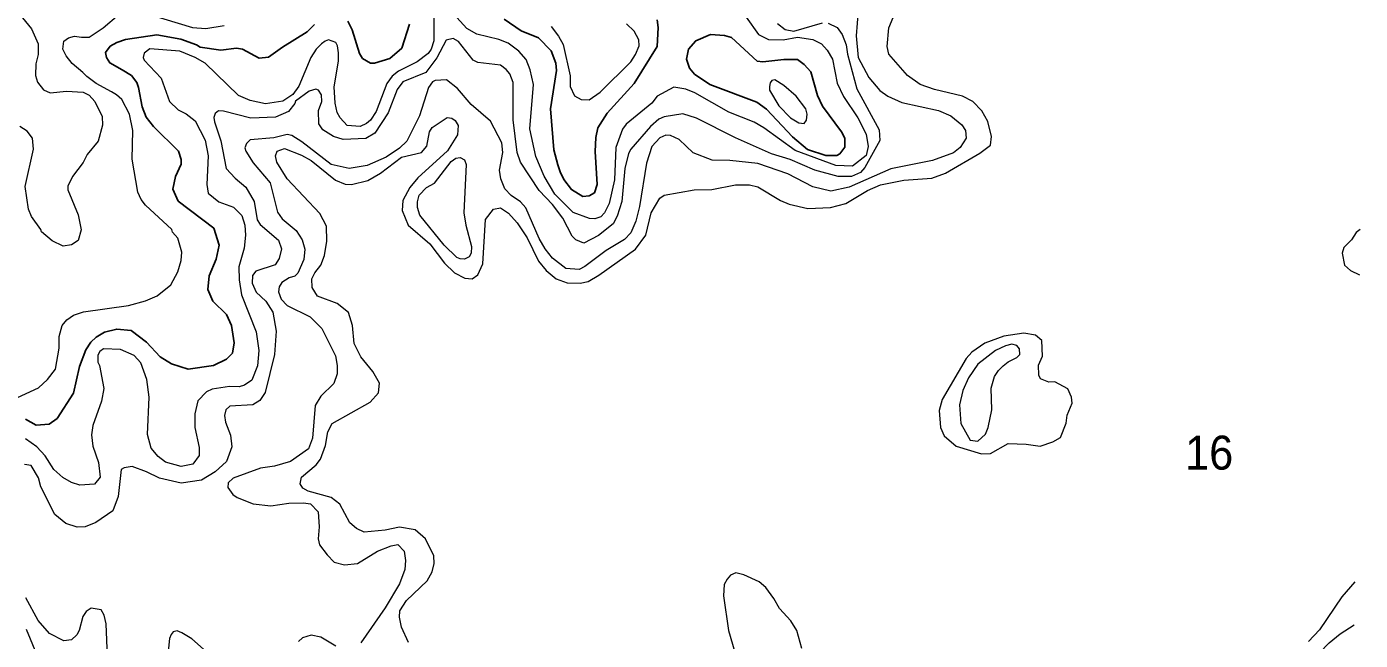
# Model space of a CAD drawing. Extents: x 673.6 to 698.9, y 7012 to 7040.1.
# Drawn here: x 695.502 to 698.642, y 7022.853 to 7024.299 of the extents above; entities that cross this region are included whole.
import ezdxf

# ---------------------------------------------------------------- set-up
doc = ezdxf.new("R2010")
doc.units = 0
doc.header["$LTSCALE"] = 0.032
doc.layers.add('1', color=7, linetype='Continuous', lineweight=25)
doc.layers.add('2', color=7, linetype='Continuous', lineweight=13)
doc.layers.add('21', color=7, linetype='Continuous')

msp = doc.modelspace()

# ---------------------------------------------------------------- linework, layer by layer
at = {"layer": '1'}
for points in [[(696.1792, 7024.3044), (696.1622, 7024.2869), (696.1045, 7024.2508), (696.0713, 7024.2273), (696.0491, 7024.2248), (696.0104, 7024.2458), (695.9957, 7024.2489), (695.9587, 7024.2442), (695.9107, 7024.2506), (695.9017, 7024.2566), (695.8651, 7024.2694), (695.8083, 7024.2802)], [(696.4032, 7024.3049), (696.385, 7024.2488), (696.3572, 7024.2244), (696.3212, 7024.2129), (696.3116, 7024.2129), (696.2926, 7024.2243), (696.2853, 7024.2361), (696.2684, 7024.2918), (696.2584, 7024.3118)], [(696.9865, 7024.3152), (696.9891, 7024.2971), (696.9867, 7024.2521), (696.9322, 7024.1649), (696.8686, 7024.0955), (696.8465, 7024.0609), (696.842, 7024.0379), (696.8405, 7024.005), (696.8453, 7023.9273), (696.839, 7023.9079), (696.8265, 7023.901), (696.8112, 7023.899), (696.7846, 7023.9155), (696.7667, 7023.939), (696.758, 7023.9571), (696.7523, 7023.9738), (696.7435, 7024.0088), (696.7353, 7024.1053), (696.7492, 7024.1963), (696.7482, 7024.2129), (696.7369, 7024.2421), (696.707, 7024.2731), (696.6666, 7024.2892), (696.6259, 7024.3167)], [(695.8083, 7024.2802), (695.7347, 7024.2688), (695.7138, 7024.2615), (695.6981, 7024.253), (695.6876, 7024.238), (695.6897, 7024.2263)], [(695.6897, 7024.2263), (695.6975, 7024.2139), (695.727, 7024.1973), (695.749, 7024.1839), (695.7615, 7024.1673), (695.7649, 7024.1555), (695.7735, 7024.1102), (695.7831, 7024.086), (695.8002, 7024.0638), (695.8593, 7024.0062), (695.8658, 7023.9862), (695.8658, 7023.9754), (695.8525, 7023.9463), (695.8462, 7023.9167), (695.8588, 7023.8884), (695.9428, 7023.8244), (695.9551, 7023.7841), (695.9481, 7023.7514), (695.9318, 7023.7125), (695.9283, 7023.6796), (695.9404, 7023.6528), (695.972, 7023.621), (695.9841, 7023.5949), (695.9907, 7023.5542), (695.9863, 7023.53), (695.9723, 7023.5159), (695.9418, 7023.5006), (695.8822, 7023.4923), (695.8432, 7023.5052), (695.8158, 7023.521), (695.7838, 7023.5561), (695.7475, 7023.5833), (695.7138, 7023.5867), (695.6851, 7023.5793), (695.6654, 7023.5677), (695.6525, 7023.5557), (695.6414, 7023.5379), (695.6262, 7023.4989), (695.6119, 7023.4356), (695.5738, 7023.3761), (695.5548, 7023.3623), (695.5243, 7023.36), (695.4987, 7023.3741)]]:
    msp.add_lwpolyline(points, dxfattribs=at)
msp.add_lwpolyline([(697.285, 7024.2219), (697.2352, 7024.2162), (697.2221, 7024.2178), (697.1613, 7024.2737), (697.1452, 7024.2786), (697.1121, 7024.281), (697.0775, 7024.2656), (697.0601, 7024.2465), (697.0558, 7024.2228), (697.0628, 7024.2016), (697.0742, 7024.1873), (697.1108, 7024.1631), (697.2209, 7024.1211), (697.2438, 7024.1046), (697.305, 7024.04), (697.3402, 7024.0095), (697.3837, 7023.9955), (697.4092, 7023.9959), (697.4165, 7023.9994), (697.4288, 7024.0155), (697.4288, 7024.0366), (697.4209, 7024.0516), (697.3756, 7024.112), (697.3642, 7024.1369), (697.3481, 7024.1931), (697.3326, 7024.2104), (697.317, 7024.2218)], close=True, dxfattribs=at)
at = {"layer": '2'}
for points in [[(697.4624, 7024.3678), (697.455, 7024.2774)], [(695.4804, 7023.4259), (695.5294, 7023.4485), (695.551, 7023.4682), (695.57, 7023.4925), (695.5782, 7023.542), (695.5784, 7023.5694), (695.5857, 7023.5949), (695.5961, 7023.6086), (695.6118, 7023.6197), (695.6354, 7023.6277), (695.7417, 7023.6419), (695.7817, 7023.6531), (695.809, 7023.6651), (695.8416, 7023.691), (695.8575, 7023.7213), (695.8659, 7023.7482), (695.8674, 7023.768), (695.8574, 7023.8006), (695.8455, 7023.8151), (695.8439, 7023.8213), (695.7819, 7023.8787), (695.7712, 7023.8919), (695.7637, 7023.9096), (695.75, 7023.9874), (695.7514, 7024.0542), (695.7442, 7024.0929), (695.726, 7024.1274), (695.7134, 7024.1386), (695.7015, 7024.1457), (695.6656, 7024.1651), (695.6432, 7024.1817), (695.6339, 7024.1909), (695.6087, 7024.2121), (695.5945, 7024.2302), (695.5873, 7024.2465), (695.5896, 7024.2649), (695.6004, 7024.2732), (695.6141, 7024.2771), (695.631, 7024.2745), (695.6493, 7024.2744), (695.682, 7024.2968), (695.7185, 7024.3277)], [(695.4846, 7024.3285), (695.5131, 7024.2937), (695.5289, 7024.2585), (695.5289, 7024.2337), (695.5234, 7024.212), (695.5224, 7024.1845), (695.5275, 7024.1681), (695.5413, 7024.1504), (695.5572, 7024.1431), (695.5953, 7024.1472), (695.6346, 7024.1448), (695.6493, 7024.1376), (695.662, 7024.1232), (695.6796, 7024.0877), (695.68, 7024.0674), (695.6701, 7024.0296), (695.6442, 7023.9979), (695.6347, 7023.9792), (695.6098, 7023.9459), (695.5989, 7023.9234), (695.5991, 7023.9145), (695.6227, 7023.8559), (695.6298, 7023.8205), (695.6233, 7023.7955), (695.6077, 7023.7848), (695.5876, 7023.7824), (695.5622, 7023.7949), (695.5364, 7023.816), (695.5353, 7023.8217), (695.5132, 7023.8517), (695.5061, 7023.8691), (695.4985, 7023.9224), (695.5182, 7024.0107), (695.5155, 7024.0365), (695.5031, 7024.0528), (695.4859, 7024.0642)], [(695.757, 7024.3378), (695.8922, 7024.2972), (695.924, 7024.2951), (695.9669, 7024.3018)], [(696.4608, 7024.3308), (696.4607, 7024.2656), (696.454, 7024.2464), (696.4469, 7024.2361), (696.421, 7024.216), (696.3776, 7024.1943), (696.3623, 7024.1826), (696.3498, 7024.165), (696.3249, 7024.0993), (696.3115, 7024.0792), (696.3024, 7024.0711), (696.287, 7024.064), (696.2566, 7024.0667), (696.24, 7024.0845), (696.233, 7024.0968), (696.2281, 7024.1187), (696.2257, 7024.1575), (696.2364, 7024.2178), (696.2364, 7024.2379), (696.234, 7024.2543), (696.2297, 7024.2621), (696.2129, 7024.2678), (696.2046, 7024.2654), (696.1957, 7024.2587), (696.1835, 7024.2464), (696.171, 7024.2267), (696.1429, 7024.1591), (696.1282, 7024.1392), (696.1047, 7024.1238)], [(697.1957, 7024.3219), (697.2251, 7024.2809), (697.2484, 7024.2691), (697.283, 7024.2683), (697.3171, 7024.2744), (697.3531, 7024.2692), (697.3735, 7024.2585), (697.3871, 7024.2439), (697.3992, 7024.2227), (697.4105, 7024.1659), (697.4252, 7024.1348), (697.4593, 7024.0842), (697.4785, 7024.0463), (697.483, 7024.017), (697.4783, 7023.9956), (697.4466, 7023.9705), (697.4075, 7023.9722), (697.3112, 7024.0071), (697.2379, 7024.0612), (697.2151, 7024.074), (697.1549, 7024.0975), (697.0754, 7024.143), (697.0541, 7024.152), (697.0254, 7024.157), (696.9865, 7024.1354), (696.974, 7024.1191), (696.9138, 7024.0693), (696.9046, 7024.0576), (696.889, 7024.0144), (696.8864, 7023.9381), (696.8731, 7023.8822), (696.8622, 7023.8602), (696.8536, 7023.8514), (696.8394, 7023.8465), (696.8271, 7023.8469), (696.7885, 7023.8617), (696.7457, 7023.9049), (696.7202, 7023.9473), (696.701, 7023.9936), (696.6868, 7024.0584), (696.6949, 7024.1627), (696.6876, 7024.1978), (696.678, 7024.2217), (696.6607, 7024.2414), (696.6354, 7024.2603), (696.6134, 7024.2688), (696.5617, 7024.2817), (696.5386, 7024.2952), (696.5071, 7024.3293)], [(697.389, 7024.3073), (697.4104, 7024.297), (697.4221, 7024.2804), (697.4318, 7024.2564), (697.4349, 7024.2345), (697.457, 7024.1526), (697.509, 7024.0558), (697.511, 7024.0312), (697.4752, 7023.967), (697.465, 7023.9558), (697.4439, 7023.9461), (697.4127, 7023.9458), (697.3576, 7023.961), (697.3, 7023.9863), (697.2559, 7023.9994), (697.1713, 7024.0375), (697.0791, 7024.0837), (697.0472, 7024.0937), (697.0029, 7024.0869), (696.9908, 7024.0813), (696.971, 7024.0639), (696.9247, 7024.0107), (696.9189, 7024.0003), (696.9102, 7023.9647), (696.9035, 7023.8871), (696.892, 7023.8526), (696.8825, 7023.8348), (696.8481, 7023.8071), (696.8139, 7023.7889), (696.7951, 7023.7967), (696.7862, 7023.8059), (696.7646, 7023.8483), (696.7404, 7023.8806), (696.7087, 7023.9131), (696.6643, 7023.9801), (696.6568, 7024.0026), (696.6472, 7024.0794), (696.6474, 7024.1678), (696.6392, 7024.1879), (696.6313, 7024.1985), (696.6176, 7024.2087), (696.5644, 7024.215), (696.5531, 7024.2204), (696.519, 7024.2645), (696.5058, 7024.271), (696.4893, 7024.2675), (696.4679, 7024.2259), (696.442, 7024.191), (696.3879, 7024.1692), (696.3746, 7024.1508), (696.353, 7024.0959), (696.322, 7024.0479), (696.3004, 7024.0356), (696.2468, 7024.033), (696.2245, 7024.0402), (696.199, 7024.0559), (696.1895, 7024.0702), (696.1888, 7024.1014), (696.1969, 7024.1229), (696.1963, 7024.1388)], [(696.4003, 7023.8313), (696.4515, 7023.7874), (696.4857, 7023.7418), (696.5096, 7023.7191), (696.5335, 7023.707), (696.5508, 7023.7051), (696.5639, 7023.7146), (696.5757, 7023.7404), (696.5826, 7023.8451), (696.6011, 7023.8691), (696.6172, 7023.8725), (696.6366, 7023.8595), (696.6571, 7023.8373), (696.6801, 7023.802), (696.707, 7023.7468), (696.7249, 7023.7244), (696.7489, 7023.705), (696.7743, 7023.6958), (696.8055, 7023.6952), (696.8241, 7023.6987), (696.8492, 7023.7134), (696.9352, 7023.7751), (696.96, 7023.808), (696.9725, 7023.8605), (696.993, 7023.8953), (697.003, 7023.902), (697.0738, 7023.9145), (697.1153, 7023.9155), (697.1709, 7023.9269), (697.204, 7023.9269), (697.2236, 7023.9219), (697.2773, 7023.8893), (697.2977, 7023.8809), (697.3414, 7023.8711), (697.3947, 7023.8735), (697.4306, 7023.8825), (697.4816, 7023.9131), (697.5122, 7023.9264), (697.5675, 7023.9376), (697.633, 7023.9426), (697.6651, 7023.9539), (697.7467, 7024.0012), (697.7713, 7024.0198), (697.7739, 7024.0408), (697.7655, 7024.0758), (697.7514, 7024.1005), (697.7299, 7024.1231), (697.7058, 7024.1351), (697.6392, 7024.1513), (697.606, 7024.1629), (697.5762, 7024.1839), (697.5318, 7024.2343), (697.5283, 7024.2523), (697.5323, 7024.2964), (697.5425, 7024.3209)], [(696.7367, 7024.2994), (696.7545, 7024.2767), (696.7648, 7024.2572), (696.7813, 7024.183), (696.782, 7024.1581), (696.7921, 7024.1366), (696.8073, 7024.1275), (696.8267, 7024.1266), (696.8524, 7024.1452), (696.9248, 7024.2167), (696.9357, 7024.2335), (696.9439, 7024.2544), (696.9437, 7024.2684), (696.9324, 7024.2885), (696.9146, 7024.3055)], [(697.2696, 7024.3064), (697.2878, 7024.2925), (697.3081, 7024.2887), (697.3762, 7024.3082)], [(697.455, 7024.2774), (697.46, 7024.2264), (697.4851, 7024.1795), (697.5111, 7024.1486), (697.5297, 7024.1353), (697.5628, 7024.1203)], [(695.8987, 7024.2268), (695.8622, 7024.2416), (695.7919, 7024.247), (695.7787, 7024.2364), (695.7764, 7024.2268), (695.7782, 7024.2199), (695.8187, 7024.1776), (695.8385, 7024.1228), (695.8584, 7024.1036), (695.8774, 7024.0937), (695.8985, 7024.0774), (695.9222, 7024.0315), (695.929, 7023.9951), (695.9259, 7023.9274), (695.9294, 7023.907), (695.9545, 7023.8867), (695.9888, 7023.8737), (696.0088, 7023.8543), (696.0155, 7023.8313), (696.017, 7023.8083), (696.0137, 7023.7774), (696.0015, 7023.7334), (696.0021, 7023.703), (696.0075, 7023.6677), (696.0424, 7023.5801), (696.0482, 7023.5365), (696.0456, 7023.5005), (696.0318, 7023.4662), (696.0148, 7023.4543), (696.0019, 7023.4503), (695.9792, 7023.4511), (695.9386, 7023.4452), (695.9251, 7023.4388), (695.9048, 7023.4178), (695.8979, 7023.387), (695.8978, 7023.3545), (695.9076, 7023.3081), (695.9077, 7023.2888), (695.893, 7023.2683), (695.8654, 7023.263), (695.8286, 7023.2735), (695.8114, 7023.2868), (695.7952, 7023.3065), (695.7862, 7023.3382), (695.7902, 7023.426), (695.7845, 7023.4681), (695.7704, 7023.507), (695.7546, 7023.5242), (695.7225, 7023.5383), (695.6824, 7023.5398), (695.6738, 7023.5342), (695.6695, 7023.525), (695.6695, 7023.5089), (695.6736, 7023.5008), (695.6834, 7023.447), (695.6778, 7023.4165), (695.6578, 7023.3596), (695.6547, 7023.3372), (695.6578, 7023.3107), (695.6711, 7023.2721), (695.6751, 7023.2377), (695.6619, 7023.2211), (695.627, 7023.2193), (695.6071, 7023.2253), (695.5872, 7023.2374), (695.5661, 7023.2561), (695.5451, 7023.2879), (695.5259, 7023.3095), (695.4991, 7023.3278)], [(696.1047, 7024.1238), (696.0643, 7024.1176), (696.0278, 7024.1249), (696.0008, 7024.1374), (695.9219, 7024.2135), (695.8987, 7024.2268)], [(697.5628, 7024.1203), (697.6487, 7024.102), (697.6781, 7024.0894), (697.7041, 7024.0682), (697.7124, 7024.0548), (697.7144, 7024.0363), (697.7002, 7024.0144), (697.6846, 7024.0018), (697.6346, 7023.9837), (697.537, 7023.9646), (697.4383, 7023.921), (697.3956, 7023.9113), (697.3532, 7023.922), (697.294, 7023.9523), (697.2233, 7023.977), (697.1576, 7023.9836), (697.1161, 7023.9843), (697.0711, 7024.0019), (697.0381, 7024.0331), (697.0181, 7024.0427), (697.0067, 7024.0433), (696.9931, 7024.0375), (696.9741, 7024.0172), (696.9617, 7023.9777), (696.945, 7023.8755), (696.9362, 7023.8408), (696.9242, 7023.8136), (696.9096, 7023.7975), (696.8665, 7023.7722), (696.8164, 7023.7341), (696.8027, 7023.7272), (696.7714, 7023.7298), (696.7399, 7023.7538), (696.7224, 7023.7755), (696.7083, 7023.7999), (696.6775, 7023.872), (696.6648, 7023.8864), (696.6427, 7023.9011), (696.6279, 7023.9169), (696.6184, 7023.9407), (696.6153, 7023.9611), (696.6234, 7024.0029), (696.621, 7024.0255), (696.5941, 7024.0765), (696.5487, 7024.1159), (696.5161, 7024.1535), (696.4906, 7024.1741), (696.4639, 7024.1725), (696.4577, 7024.1694), (696.4481, 7024.156), (696.4269, 7024.0893), (696.3968, 7024.0293), (696.3801, 7024.0127), (696.3481, 7023.9915), (696.3039, 7023.9719), (696.2612, 7023.9648), (696.2186, 7023.9741), (696.1498, 7024.028), (696.1264, 7024.0429), (696.1149, 7024.0451), (696.0841, 7024.037), (696.028, 7024.0324), (696.0195, 7024.0238), (696.0156, 7024.0138), (696.0175, 7024.006), (696.0351, 7023.9785), (696.0755, 7023.9311), (696.0926, 7023.8623), (696.1036, 7023.8462), (696.1361, 7023.8192), (696.1509, 7023.797), (696.1566, 7023.7748), (696.1542, 7023.751), (696.1403, 7023.7183), (696.1332, 7023.7114), (696.1202, 7023.7073), (696.1027, 7023.6961), (696.0964, 7023.6866), (696.0951, 7023.6742), (696.101, 7023.6572), (696.1154, 7023.6422), (696.169, 7023.6153), (696.1968, 7023.5878), (696.2287, 7023.5233), (696.2331, 7023.5009), (696.2331, 7023.4812), (696.2254, 7023.4585), (696.1948, 7023.4283), (696.1815, 7023.4063), (696.1747, 7023.3296), (696.1656, 7023.3049), (696.1234, 7023.2745), (696.0852, 7023.2639), (696.0527, 7023.2592), (695.9881, 7023.2353)], [(696.1963, 7024.1388), (696.1892, 7024.1497), (696.1825, 7024.1519), (696.1667, 7024.1471), (696.1347, 7024.124), (696.1335, 7024.1181)], [(696.1335, 7024.1181), (696.1187, 7024.0997), (696.0878, 7024.0859), (696.0295, 7024.0839), (695.9654, 7024.0998), (695.9532, 7024.1011), (695.9455, 7024.0949), (695.9426, 7024.0855), (695.9438, 7024.0752), (695.9587, 7024.0301), (695.9718, 7023.9651), (695.9926, 7023.9423), (696.0175, 7023.9213), (696.0375, 7023.887), (696.0444, 7023.8444), (696.0518, 7023.8332), (696.0949, 7023.7962), (696.1016, 7023.7758), (696.0967, 7023.7528), (696.087, 7023.7381), (696.0415, 7023.7228), (696.0333, 7023.7127), (696.0327, 7023.6947), (696.0423, 7023.6734), (696.0647, 7023.6524), (696.0816, 7023.6265), (696.0893, 7023.5818), (696.0851, 7023.5268), (696.0631, 7023.4375), (696.0506, 7023.4183), (696.0347, 7023.4084), (695.9805, 7023.4052), (695.9705, 7023.3966), (695.9678, 7023.383), (695.9699, 7023.3673), (695.9817, 7023.3366), (695.9849, 7023.309), (695.9723, 7023.2751), (695.9457, 7023.2502), (695.9133, 7023.2309), (695.8655, 7023.2236), (695.8142, 7023.2353), (695.7839, 7023.2505), (695.7499, 7023.2627), (695.7311, 7023.2596), (695.7247, 7023.2556), (695.7171, 7023.1926), (695.7046, 7023.1585), (695.665, 7023.1313), (695.6399, 7023.1208), (695.621, 7023.12), (695.5944, 7023.1284), (695.5685, 7023.1495), (695.5349, 7023.2147), (695.5297, 7023.2366), (695.5127, 7023.2656), (695.4963, 7023.2679)], [(696.4012, 7022.8486), (696.3846, 7022.8842), (696.3795, 7022.9076), (696.3809, 7022.9229), (696.3959, 7022.9474), (696.4447, 7022.9936), (696.4565, 7023.0144), (696.4615, 7023.0346), (696.4608, 7023.0526), (696.4408, 7023.0923), (696.417, 7023.1137), (696.3795, 7023.1198), (696.3462, 7023.113), (696.2967, 7023.1085), (696.2781, 7023.1168), (696.2624, 7023.1303), (696.2394, 7023.1743), (696.2192, 7023.1896), (696.1647, 7023.2047), (696.1523, 7023.2116), (696.1461, 7023.2222), (696.1491, 7023.2381), (696.1838, 7023.2671), (696.1936, 7023.2801), (696.2057, 7023.3127), (696.2109, 7023.3448), (696.2211, 7023.3642), (696.3109, 7023.4146), (696.3301, 7023.4367), (696.3325, 7023.4589), (696.3169, 7023.487), (696.2887, 7023.5216), (696.273, 7023.5526), (696.2693, 7023.5953), (696.26, 7023.6255), (696.2326, 7023.6473), (696.1863, 7023.6641), (696.1741, 7023.685), (696.1733, 7023.7049), (696.18, 7023.7192), (696.1943, 7023.7376), (696.2028, 7023.7597), (696.2084, 7023.7938), (696.2076, 7023.8289), (696.1925, 7023.8589), (696.1152, 7023.9407), (696.0912, 7023.98), (696.0877, 7023.9952), (696.0916, 7024.0061), (696.1091, 7024.012), (696.1489, 7023.9966), (696.1718, 7023.9842), (696.2287, 7023.9379), (696.252, 7023.9278), (696.2668, 7023.927), (696.3053, 7023.9371), (696.3348, 7023.9544), (696.3847, 7023.9918), (696.4313, 7024.0028), (696.4442, 7024.0173), (696.45, 7024.0515), (696.4567, 7024.0617), (696.4923, 7024.0855), (696.5032, 7024.0838), (696.5112, 7024.0784), (696.5182, 7024.066), (696.5165, 7024.0446), (696.4931, 7024.0069)], [(696.4931, 7024.0069), (696.4228, 7023.943), (696.4039, 7023.92), (696.3878, 7023.8894), (696.386, 7023.8658), (696.4003, 7023.8313)], [(698.6423, 7023.8216), (698.6327, 7023.8143), (698.6216, 7023.7967), (698.6036, 7023.7787), (698.5998, 7023.7653), (698.6048, 7023.7373), (698.6194, 7023.7244), (698.6406, 7023.7143)], [(695.9881, 7023.2353), (695.9762, 7023.2246), (695.9754, 7023.2135), (695.9876, 7023.1972), (695.9972, 7023.1898), (696.0351, 7023.175)], [(696.0351, 7023.175), (696.0767, 7023.1701), (696.119, 7023.1766), (696.1538, 7023.1774), (696.17, 7023.1748), (696.188, 7023.1558), (696.1905, 7023.1208), (696.1879, 7023.0922), (696.1916, 7023.0784), (696.2091, 7023.0545), (696.2261, 7023.0378), (696.2501, 7023.0313), (696.281, 7023.0344), (696.3283, 7023.0635), (696.3601, 7023.0759), (696.3758, 7023.0788), (696.3911, 7023.0633), (696.3942, 7023.0418), (696.3926, 7023.0201), (696.38, 7022.9865), (696.3458, 7022.9302), (696.2887, 7022.8478)], [(697.3269, 7022.834), (697.3156, 7022.8764), (697.3014, 7022.8997), (697.2743, 7022.9285), (697.2611, 7022.9523), (697.2425, 7022.9775), (697.2269, 7022.9911), (697.1909, 7023.0081), (697.1719, 7023.0126), (697.1589, 7023.0067), (697.1515, 7022.9972), (697.1446, 7022.9847), (697.1429, 7022.9586), (697.1541, 7022.8762), (697.1856, 7022.7692)], [(698.6291, 7022.9909), (698.5989, 7022.9555), (698.5458, 7022.8778), (698.5203, 7022.8507)], [(695.6925, 7022.8152), (695.689, 7022.8923), (695.6843, 7022.9126), (695.6769, 7022.925), (695.6533, 7022.9293), (695.6421, 7022.9216), (695.6342, 7022.9095), (695.6258, 7022.8768), (695.6199, 7022.8666), (695.6071, 7022.8544), (695.5895, 7022.8522), (695.5559, 7022.8696), (695.5289, 7022.9001), (695.4996, 7022.9532)], [(697.5587, 7022.594), (697.5562, 7022.6404), (697.5583, 7022.65), (697.5707, 7022.672), (697.596, 7022.6989), (697.6317, 7022.7182), (697.6641, 7022.7206), (697.7073, 7022.7029), (697.7523, 7022.6747), (697.9091, 7022.612), (697.9835, 7022.5884), (698.1533, 7022.5727), (698.1979, 7022.5768), (698.2453, 7022.5866), (698.3196, 7022.6163), (698.3585, 7022.6395), (698.4308, 7022.7044), (698.5688, 7022.8474), (698.5947, 7022.869), (698.6275, 7022.8901)], [(695.5009, 7022.88), (695.5248, 7022.8211), (695.5512, 7022.7922), (695.5995, 7022.7674), (695.6144, 7022.7506), (695.6298, 7022.7126), (695.6362, 7022.6881), (695.6676, 7022.6209), (695.6806, 7022.6001), (695.723, 7022.5552), (695.7465, 7022.5378), (695.7883, 7022.5275), (695.8376, 7022.5381)], [(695.9659, 7022.7899), (695.8908, 7022.8568), (695.8674, 7022.8709), (695.8565, 7022.8757), (695.8468, 7022.8731), (695.8422, 7022.867), (695.8379, 7022.8577), (695.8305, 7022.7818)], [(696.2302, 7022.8393), (696.1948, 7022.8608), (696.1716, 7022.8652), (696.1512, 7022.8591), (696.1422, 7022.8507)]]:
    msp.add_lwpolyline(points, dxfattribs=at)
for points in [[(697.2846, 7024.1604), (697.2634, 7024.1738), (697.2567, 7024.1722), (697.2526, 7024.167), (697.2508, 7024.1585), (697.2513, 7024.1493), (697.2731, 7024.113), (697.3001, 7024.0843), (697.3197, 7024.0723), (697.3323, 7024.0712), (697.3382, 7024.079), (697.3395, 7024.0927), (697.3364, 7024.1056), (697.3142, 7024.1351)], [(696.428, 7023.8547), (696.4221, 7023.8731), (696.4218, 7023.8865), (696.4263, 7023.9022), (696.4436, 7023.9204), (696.4625, 7023.9305), (696.5016, 7023.9816), (696.5123, 7023.9897), (696.5227, 7023.991), (696.5329, 7023.9851), (696.5369, 7023.9746), (696.5315, 7023.8605), (696.5359, 7023.8318), (696.5494, 7023.781), (696.5485, 7023.7652), (696.5436, 7023.757), (696.5331, 7023.7518), (696.5227, 7023.7519), (696.5148, 7023.7556), (696.4847, 7023.7845)], [(697.9084, 7023.4618), (697.8894, 7023.4692), (697.885, 7023.4779), (697.8841, 7023.5016), (697.8939, 7023.5231), (697.8921, 7023.5595), (697.8777, 7023.5725), (697.8499, 7023.5768), (697.8028, 7023.57), (697.7584, 7023.5534), (697.7277, 7023.5322), (697.7145, 7023.5173), (697.6574, 7023.4211), (697.6503, 7023.3945), (697.654, 7023.3552), (697.6624, 7023.335), (697.6902, 7023.3107), (697.7506, 7023.2926), (697.7713, 7023.2937), (697.8131, 7023.317), (697.8552, 7023.3155), (697.8881, 7023.3106), (697.9182, 7023.3211), (697.9363, 7023.3311), (697.9498, 7023.3648), (697.9521, 7023.3835), (697.9636, 7023.4122), (697.9618, 7023.4264), (697.9532, 7023.4458), (697.9228, 7023.4625)], [(697.7746, 7023.3962), (697.773, 7023.4473), (697.7812, 7023.4746), (697.7905, 7023.4891), (697.8011, 7023.5004), (697.8134, 7023.5093), (697.8336, 7023.5197), (697.8404, 7023.5272), (697.84, 7023.5401), (697.8336, 7023.5477), (697.8218, 7023.551), (697.8068, 7023.5471), (697.7835, 7023.5364), (697.7415, 7023.5041), (697.7199, 7023.472), (697.7063, 7023.4423), (697.6984, 7023.4079), (697.7017, 7023.364), (697.7239, 7023.3246), (697.7413, 7023.3224), (697.7598, 7023.3393), (697.7661, 7023.3546)]]:
    msp.add_lwpolyline(points, close=True, dxfattribs=at)

# ---------------------------------------------------------------- texts
at = {"layer": '21', "width": 0.95}
msp.add_text('16', height=0.08, dxfattribs=at).set_placement((698.2299, 7023.2556))

doc.saveas('drawing.dxf')
